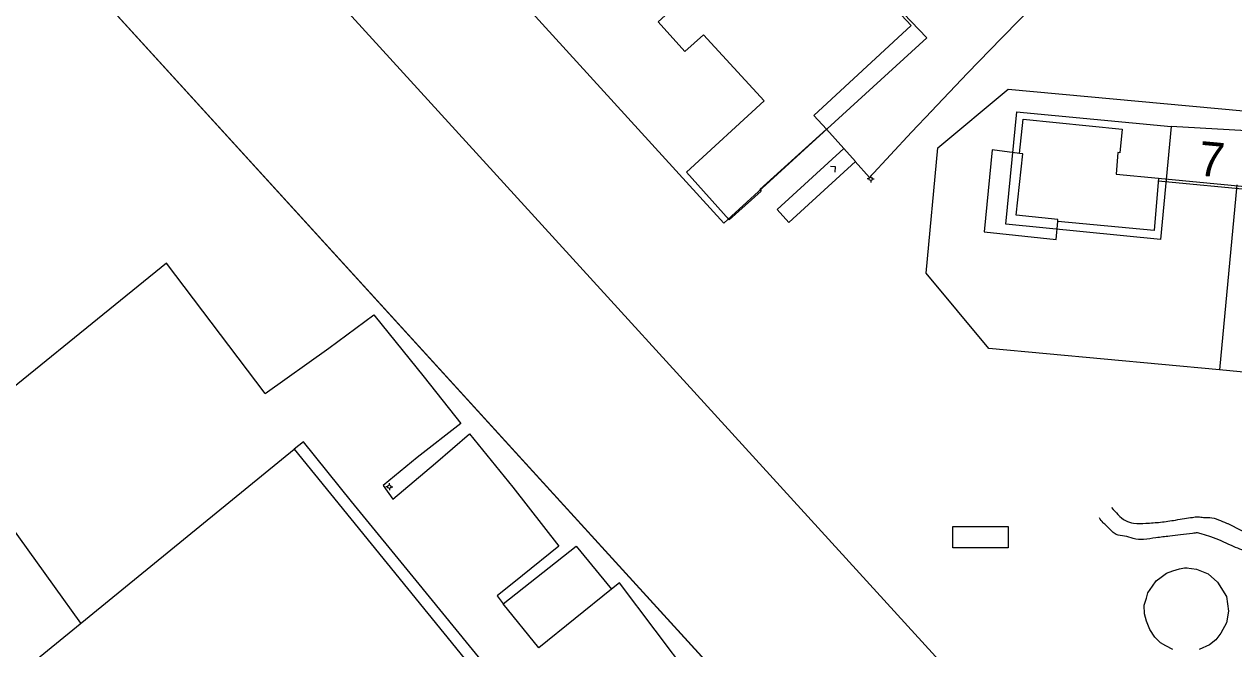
# Model space of a CAD drawing. Extents: x 1517229 to 1518128, y 6494851 to 6495271.
# Drawn here: x 1517875.8 to 1518015.9, y 6495054.4 to 6495126.7 of the extents above; entities that cross this region are included whole.
import ezdxf

# ---------------------------------------------------------------- set-up
doc = ezdxf.new("R2010")
doc.units = 0
doc.layers.add('Karta', color=7, linetype='Continuous')

msp = doc.modelspace()

# ---------------------------------------------------------------- linework, layer by layer
at = {"layer": 'Karta'}
for p, q in [((1517860.04, 6495186.49), (1518013.12, 6495018.67)), ((1517980.37, 6495125.12), (1517954.43, 6495152.21)), ((1517881.78, 6495132.98), (1517993.7, 6495010.28)), ((1517931.59, 6495131.38), (1517956.86, 6495103.68)), ((1517956.86, 6495103.68), (1517980.37, 6495125.12)), ((1517981.65, 6495112.4), (1517989.81, 6495119.18)), ((1517989.81, 6495119.18), (1518017.06, 6495116.66)), ((1517968.76, 6495114.56), (1517970.77, 6495112.33)), ((1517980.31, 6495097.86), (1517981.65, 6495112.4)), ((1517973.67, 6495108.79), (1517973.47, 6495108.79)), ((1517973.87, 6495108.99), (1517973.87, 6495109.19)), ((1517973.87, 6495108.59), (1517973.87, 6495108.39)), ((1517974.07, 6495108.79), (1517974.27, 6495108.79)), ((1518016.27, 6495108.09), (1518014.29, 6495086.68)), ((1517987.54, 6495089.15), (1517980.31, 6495097.86)), ((1518014.29, 6495086.68), (1517987.54, 6495089.15)), ((1518036.62, 6495084.62), (1518014.29, 6495086.68)), ((1517918.1, 6495073.36), (1517918.1, 6495073.56)), ((1517917.9, 6495073.16), (1517917.7, 6495073.16)), ((1517918.1, 6495072.96), (1517918.1, 6495072.76)), ((1517918.3, 6495073.16), (1517918.5, 6495073.16)), ((1517930.6, 6495060.51), (1517931.3, 6495059.58))]:
    msp.add_line(p, q, dxfattribs=at)
for points in [[(1517844.68, 6495173.66), (1517881.78, 6495132.98), (1517993.7, 6495010.28)], [(1517949.24, 6495126.98), (1517960.49, 6495137.19), (1517963.66, 6495133.86), (1517967.99, 6495137.88), (1517978.54, 6495126.55), (1517967.29, 6495116.15), (1517968.76, 6495114.56), (1517961.02, 6495107.55), (1517961.18, 6495107.37), (1517957.48, 6495104.06), (1517952.53, 6495109.56), (1517961.53, 6495117.85), (1517954.49, 6495125.49), (1517952.35, 6495123.56), (1517949.24, 6495126.99)], [(1517980.9, 6495116.52), (1517980.87, 6495116.58), (1517985.09, 6495121.02), (1517989.01, 6495125.09), (1517993.39, 6495129.56)], [(1518036.3, 6495130.68), (1518018.77, 6495114.27), (1518008.68, 6495114.85)], [(1517972.08, 6495110.8), (1517973.72, 6495108.95), (1517978.61, 6495114.2), (1517980.96, 6495116.67)], [(1517990.75, 6495116.55), (1518008.68, 6495114.85), (1518007.46, 6495101.76), (1517989.54, 6495103.56), (1517990.79, 6495116.55)], [(1517991.55, 6495115.72), (1518003, 6495114.56), (1518002.75, 6495111.83), (1518002.52, 6495111.84), (1518002.3, 6495109.35), (1518007.2, 6495108.88), (1518006.7, 6495102.82), (1517995.56, 6495103.88), (1517995.56, 6495104.1), (1517990.72, 6495104.58), (1517991.48, 6495111.71), (1517991.12, 6495111.75), (1517991.55, 6495115.72)], [(1518007.16, 6495108.89), (1518018.47, 6495107.78), (1518025.88, 6495114.63)], [(1518007.18, 6495108.58), (1518018.58, 6495107.47), (1518026.08, 6495114.41)], [(1517970.77, 6495112.33), (1517972.09, 6495110.82), (1517964.37, 6495103.76), (1517963.04, 6495105.26), (1517970.77, 6495112.33)], [(1517991.12, 6495111.75), (1517987.93, 6495112.16), (1517987, 6495102.66), (1517995.34, 6495101.76), (1517995.56, 6495103.88)], [(1517969.76, 6495109.59), (1517969.8, 6495110.18), (1517969.2, 6495110.22)], [(1517903.73, 6495083.96), (1517892.28, 6495099.05), (1517867.02, 6495078.59), (1517882.33, 6495057.34)], [(1517903.73, 6495083.96), (1517911.08, 6495089.2), (1517916.31, 6495093.04), (1517922.14, 6495085.82), (1517926.39, 6495080.47), (1517921.34, 6495076.54), (1517917.37, 6495073.29), (1517918.5, 6495071.7), (1517923.46, 6495075.88), (1517927.37, 6495079.26), (1517932.41, 6495073.1), (1517937.74, 6495066.29), (1517933.53, 6495062.89), (1517930.6, 6495060.51)], [(1517933.73, 6495045.66), (1517934.33, 6495046.26), (1517927.37, 6495054.74), (1517921.21, 6495062.29), (1517913.73, 6495071.44), (1517908.14, 6495078.37), (1517907.09, 6495077.52)], [(1517870.88, 6495048), (1517907.09, 6495077.52), (1517933.35, 6495045.23)], [(1517931.3, 6495059.58), (1517939.76, 6495066.27), (1517943.82, 6495061.29), (1517935.42, 6495054.49), (1517931.27, 6495059.6)], [(1518008.86, 6495054.3), (1518008.08, 6495054.72), (1518007.44, 6495055.08), (1518006.78, 6495055.74), (1518006.2, 6495056.62), (1518005.84, 6495057.59), (1518005.6, 6495058.43), (1518005.57, 6495059.46), (1518005.84, 6495060.24), (1518005.99, 6495060.88), (1518006.51, 6495061.66), (1518006.96, 6495062.27), (1518007.53, 6495062.69), (1518008.14, 6495063.14), (1518008.89, 6495063.41), (1518009.64, 6495063.63), (1518010.22, 6495063.75), (1518010.55, 6495063.75)], [(1518010.46, 6495063.78), (1518011.61, 6495063.6), (1518012.96, 6495063.05), (1518014.05, 6495062.12), (1518015.08, 6495060.43), (1518015.32, 6495058.74), (1518015.11, 6495057.38), (1518014.44, 6495056.2), (1518013.87, 6495055.44), (1518013.12, 6495054.84), (1518011.94, 6495054.3)], [(1517942.87, 6495042.85), (1517953.03, 6495051.06), (1517944.76, 6495062.04), (1517943.82, 6495061.29)]]:
    msp.add_lwpolyline(points, dxfattribs=at)
msp.add_lwpolyline([(1517983.37, 6495068.53), (1517989.8, 6495068.53), (1517989.8, 6495066.06), (1517983.37, 6495066.06)], close=True, dxfattribs=at)
for centre in [(1517973.87, 6495108.79), (1517918.1, 6495073.16)]:
    msp.add_circle(centre, 0.2, dxfattribs=at)
for points in [[(1518001.78, 6495070.73), (1518002.52, 6495069.92), (1518003.4, 6495069.23), (1518004.33, 6495068.92), (1518005.76, 6495068.92), (1518007.44, 6495069.05), (1518009.18, 6495069.3), (1518010.23, 6495069.48), (1518011.17, 6495069.61), (1518011.79, 6495069.67), (1518012.41, 6495069.61), (1518013.4, 6495069.55), (1518014.4, 6495069.23), (1518015.33, 6495068.86)], [(1518027.99, 6495063.11), (1518025.73, 6495063.76), (1518024.2, 6495064.17), (1518023.52, 6495064.38), (1518022.28, 6495064.48), (1518020.88, 6495064.6), (1518019.98, 6495064.73), (1518019.48, 6495064.7), (1518018.89, 6495064.85), (1518017.58, 6495065.5), (1518015.66, 6495066.34), (1518013.29, 6495067.34), (1518012.27, 6495067.65), (1518011.74, 6495067.8), (1518011.15, 6495067.74), (1518009.78, 6495067.59), (1518008.51, 6495067.43), (1518006.92, 6495067.24), (1518005.49, 6495067.06), (1518004.28, 6495067.15), (1518003.29, 6495067.43), (1518002.29, 6495067.62), (1518001.86, 6495067.96), (1518001.17, 6495068.64), (1518000.8, 6495068.99), (1518000.37, 6495069.54)], [(1518015.25, 6495068.89), (1518017.77, 6495067.59), (1518019.01, 6495067), (1518020.13, 6495066.75), (1518021.34, 6495066.53), (1518022.65, 6495066.44), (1518023.77, 6495066.34), (1518024.36, 6495066.25), (1518025.1, 6495066), (1518026.97, 6495065.41), (1518028.31, 6495065.04)]]:
    msp.add_spline(points, degree=3, dxfattribs=at)

# ---------------------------------------------------------------- texts
msp.add_text('7', height=4, rotation=354.8003, dxfattribs=at).set_placement((1518011.71, 6495109.2))

doc.saveas('drawing.dxf')
